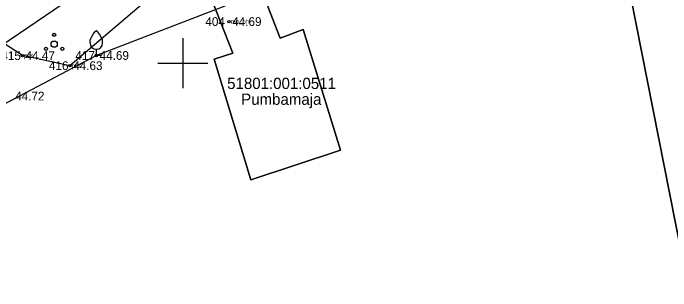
# Model space of a CAD drawing. Extents: x 505800 to 507326, y 6540058 to 6542128.
# Drawn here: x 506036.4 to 506089, y 6540181.8 to 6540204 of the extents above; entities that cross this region are included whole.
import ezdxf

# ---------------------------------------------------------------- set-up
doc = ezdxf.new("R2010")
doc.units = 0
for name, color, linetype in [('HALJASTUS', 7, 'Continuous'), ('KORGUS-EH2000', 7, 'Continuous'), ('MAAMUDEL', 7, 'Continuous'), ('MOOTKORG-EH2000', 7, 'Continuous'), ('MOOTMPUNKT', 7, 'Continuous'), ('MOOTNR', 7, 'Continuous'), ('MOOTPIIR', 7, 'Continuous'), ('MPOHULIIN', 7, 'Continuous'), ('PIIR', 7, 'Continuous'), ('PUU', 7, 'Continuous'), ('VORK', 7, 'Continuous')]:
    doc.layers.add(name, color=color, linetype=linetype)

msp = doc.modelspace()

# ---------------------------------------------------------------- linework, layer by layer
at = {"layer": 'HALJASTUS'}
msp.add_lwpolyline([(506046.677, 6540204.671), (506040.966, 6540199.801), (506037.159, 6540200.603), (506032.66, 6540203.527), (506030.725, 6540206.895), (506033.579, 6540207.906), (506043.226, 6540211.399), (506047.158, 6540212.679), (506048.085, 6540210.638), (506048.426, 6540206.794), (506046.677, 6540204.671)], dxfattribs=at)
at = {"layer": 'KORGUS-EH2000'}
for centre in [(506053.69, 6540203.325), (506043.081, 6540200.619), (506037.159, 6540200.603), (506040.966, 6540199.801)]:
    msp.add_circle(centre, 0.1, dxfattribs=at)
at = {"layer": 'MOOTMPUNKT'}
for centre in [(506053.69, 6540203.325), (506043.081, 6540200.619), (506037.159, 6540200.603), (506040.966, 6540199.801)]:
    msp.add_circle(centre, 0.1, dxfattribs=at)
at = {"layer": 'MOOTPIIR'}
msp.add_lwpolyline([(506098.399, 6540223.506), (506079.917, 6540216.55), (506066.66, 6540209.695), (506043.081, 6540200.619), (506022.167, 6540189.594), (506009.976, 6540186.473), (506006.85, 6540199.643), (506004.777, 6540209.051), (506007.93, 6540210.81), (506012.129, 6540212.088), (506014.395, 6540212.969), (506023.481, 6540210.643), (506053.328, 6540222.211), (506081.494, 6540234.9), (506083.03, 6540240.114), (506097.119, 6540244.795)], dxfattribs=at)
at = {"layer": 'MPOHULIIN'}
msp.add_lwpolyline([(506023.288, 6540193.167), (506046.819, 6540209.126), (506079.898, 6540221.464), (506112.189, 6540233.927), (506117.49, 6540230.51)], dxfattribs=at)
at = {"layer": 'PIIR'}
for points in [[(506075.94, 6540254.08), (506092.1, 6540260.96), (506133.36, 6540278.52), (506141.06, 6540246.81), (506150.17, 6540208.02), (506090.32, 6540182.64), (506081.75, 6540225.93), (506080.52, 6540231.87)], [(506053.1, 6540214.07), (506057.79, 6540202.01), (506059.62, 6540202.68), (506062.61, 6540193.04), (506055.45, 6540190.69), (506052.51, 6540200.31), (506053.99, 6540200.79), (506049.36, 6540212.6)]]:
    msp.add_lwpolyline(points, close=True, dxfattribs=at)
msp.add_lwpolyline([(506028.99, 6540136.11), (506018.19, 6540200.68), (506049.36, 6540212.6), (506053.99, 6540200.79), (506052.51, 6540200.31), (506055.45, 6540190.69), (506062.61, 6540193.04), (506059.62, 6540202.68), (506057.79, 6540202.01), (506053.1, 6540214.07), (506081.75, 6540225.93), (506090.32, 6540182.64), (506150.17, 6540208.02), (506142.88, 6540238.84), (506158.97, 6540240.95), (506187, 6540243.59), (506198.96, 6540244.45), (506208.53, 6540246.07), (506224.13, 6540249.92), (506272.39, 6540267.75)], dxfattribs=at)
at = {"layer": 'PUU'}
for p, q in [((506043.081, 6540200.619), (506043.081, 6540201.119)), ((506043.481, 6540200.619), (506043.081, 6540200.619))]:
    msp.add_line(p, q, dxfattribs=at)
for points in [[(506042.581, 6540201.619), (506042.581, 6540201.769), (506042.591, 6540201.834), (506042.626, 6540201.964), (506042.686, 6540202.084), (506042.831, 6540202.319), (506042.991, 6540202.524), (506043.081, 6540202.619)], [(506043.581, 6540201.619), (506043.581, 6540201.769), (506043.571, 6540201.834), (506043.536, 6540201.964), (506043.476, 6540202.084), (506043.331, 6540202.319), (506043.171, 6540202.524), (506043.081, 6540202.619)]]:
    msp.add_lwpolyline(points, dxfattribs=at)
for centre, radius in [((506039.701, 6540202.269), 0.125), ((506039.701, 6540201.519), 0.25), ((506039.051, 6540201.144), 0.125), ((506040.351, 6540201.144), 0.125)]:
    msp.add_circle(centre, radius, dxfattribs=at)
msp.add_arc((506043.081, 6540201.619), 0.5, 180, 0, dxfattribs=at)
at = {"layer": 'VORK'}
for p, q in [((506050, 6540202), (506050, 6540198)), ((506048, 6540200), (506052, 6540200))]:
    msp.add_line(p, q, dxfattribs=at)

# ---------------------------------------------------------------- texts
at = {"layer": 'KORGUS-EH2000'}
for s, p in [(' 44.69', (506043.081, 6540200.269)), (' 44.72', (506036.321, 6540197.022))]:
    msp.add_text(s, height=0.7, dxfattribs=at).set_placement(p)
at = {"layer": 'MAAMUDEL'}
for s, p in [(' mp_ohl', (506053.69, 6540203.15)), (' pos', (506037.159, 6540200.428)), (' pos', (506040.966, 6540199.626))]:
    msp.add_text(s, height=0.35, dxfattribs=at).set_placement(p)
at = {"layer": 'MOOTKORG-EH2000'}
for s, p in [(' 44.69', (506053.69, 6540202.975)), (' 44.47', (506037.159, 6540200.253)), (' 44.69', (506043.081, 6540200.269)), (' 44.63', (506040.966, 6540199.451)), (' 44.72', (506036.321, 6540197.022))]:
    msp.add_text(s, height=0.7, dxfattribs=at).set_placement(p)
at = {"layer": 'MOOTNR'}
for s, p in [('404 ', (506051.8, 6540202.975)), ('415 ', (506035.479, 6540200.253)), ('417 ', (506041.401, 6540200.269)), ('416 ', (506039.286, 6540199.451))]:
    msp.add_text(s, height=0.7, dxfattribs=at).set_placement(p)
at = {"layer": 'PIIR'}
for s, p in [('51801:001:0511', (506053.543, 6540197.938)), ('Pumbamaja', (506054.664, 6540196.674))]:
    msp.add_text(s, height=0.9, dxfattribs=at).set_placement(p)

doc.saveas('drawing.dxf')
